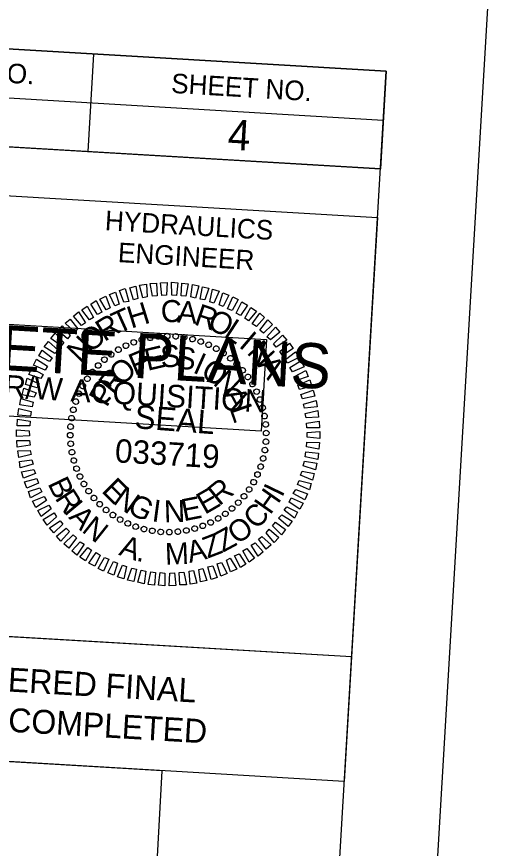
# Model space of a CAD drawing. Extents: x 2010737 to 2012732, y 444258 to 445456.
# Drawn here: x 2012611.3 to 2012732.3, y 445134 to 445346.8 of the extents above; entities that cross this region are included whole.
import ezdxf

# ---------------------------------------------------------------- set-up
doc = ezdxf.new("R2010")
doc.units = 0
for name, color, linetype in [('Sheet Clip Boundary CELL', 7, 'Continuous'), ('Sheet Data Field CELL', 7, 'Continuous'), ('Sheet Plan And Profile CELL', 7, 'Continuous'), ('Sheet Plot Border Outside CELL', 7, 'Continuous'), ('Sheet Professional Seal CELL', 7, 'Continuous'), ('Sheet Profile Grid Minor CELL', 7, 'Continuous'), ('Sheet Sticker Exception Certification CELL', 7, 'Continuous'), ('Sheet Sticker Incomplete CELL', 7, 'Continuous')]:
    doc.layers.add(name, color=color, linetype=linetype)

msp = doc.modelspace()

# ---------------------------------------------------------------- linework, layer by layer
at = {"layer": 'Sheet Clip Boundary CELL'}
msp.add_lwpolyline([(2011147.85, 444375), (2012145.7, 444317.47), (2012151.4, 444414.1), (2011981.99, 444424.08), (2012065.05, 444531.98), (2012116.09, 444528.98), (2012447, 444433.71), (2012447.13, 444434.15), (2012512.37, 444430.3), (2012650.6, 444422.19), (2012665.49, 444675.78), (2012620.99, 444678.39), (2012629.52, 444823.68), (2012643.65, 445063.27), (2012648.58, 445153.9), (2012495.5, 445162.92), (2012502.28, 445278.05), (2012302.58, 445289.82), (2012278.52, 445262.33), (2012176.97, 445268.45), (2011765.99, 445293.2), (2011771.61, 445387.92), (2011477.93, 445405.24)], dxfattribs=at)
at = {"layer": 'Sheet Plan And Profile CELL'}
for p, q in [((2012631.04, 445337.21), (2012629.57, 445312.26)), ((2012505.47, 445332.09), (2012705.17, 445320.32)), ((2012504.73, 445319.61), (2012704.44, 445307.84))]:
    msp.add_line(p, q, dxfattribs=at)
for points in [[(2012705.91, 445332.85), (2011208.51, 445421.12), (2011146.72, 444372.94), (2012644.12, 444284.67)], [(2012506.21, 445344.62), (2012705.91, 445332.85), (2012704.44, 445307.84), (2012504.73, 445319.61)], [(2012603.87, 445301.25), (2012703.7, 445295.36), (2012697.08, 445183.06), (2012597.25, 445188.94)]]:
    msp.add_lwpolyline(points, close=True, dxfattribs=at)
at = {"layer": 'Sheet Plot Border Outside CELL'}
msp.add_lwpolyline([(2010970.55, 444358.28), (2012667.61, 444258.24), (2012732.34, 445356.33), (2011035.28, 445456.37)], close=True, dxfattribs=at)
at = {"layer": 'Sheet Professional Seal CELL'}
for p, q in [((2012647.71, 445264.93), (2012647.71, 445264.93)), ((2012649.87, 445265.11), (2012649.87, 445265.11)), ((2012652.07, 445265.03), (2012652.07, 445265.03)), ((2012641.31, 445263.51), (2012641.31, 445263.51)), ((2012643.35, 445264.19), (2012643.35, 445264.19)), ((2012645.49, 445264.66), (2012645.49, 445264.66)), ((2012654.26, 445264.75), (2012654.26, 445264.75)), ((2012656.38, 445264.27), (2012656.38, 445264.27)), ((2012658.45, 445263.7), (2012658.45, 445263.7)), ((2012660.51, 445262.88), (2012660.51, 445262.88)), ((2012637.34, 445261.59), (2012637.34, 445261.59)), ((2012639.31, 445262.62), (2012639.31, 445262.62)), ((2012662.45, 445261.86), (2012662.45, 445261.86)), ((2012664.34, 445260.75), (2012664.34, 445260.75)), ((2012633.79, 445259.04), (2012633.79, 445259.04)), ((2012635.52, 445260.44), (2012635.52, 445260.44)), ((2012666.06, 445259.39), (2012666.06, 445259.39)), ((2012632.2, 445257.58), (2012632.2, 445257.58)), ((2012667.73, 445257.94), (2012667.73, 445257.94)), ((2012669.19, 445256.36), (2012669.19, 445256.36)), ((2012630.75, 445255.92), (2012630.75, 445255.92)), ((2012670.59, 445254.62), (2012670.59, 445254.62)), ((2012628.28, 445252.31), (2012628.28, 445252.31)), ((2012629.39, 445254.19), (2012629.39, 445254.19)), ((2012671.73, 445252.8), (2012671.73, 445252.8)), ((2012627.26, 445250.36), (2012627.26, 445250.36)), ((2012672.77, 445250.84), (2012672.77, 445250.84)), ((2012626.44, 445248.31), (2012626.44, 445248.31)), ((2012673.65, 445248.83), (2012673.65, 445248.83)), ((2012625.87, 445246.24), (2012625.87, 445246.24)), ((2012674.33, 445246.79), (2012674.33, 445246.79)), ((2012625.39, 445244.11), (2012625.39, 445244.11)), ((2012674.81, 445244.65), (2012674.81, 445244.65)), ((2012625.11, 445241.92), (2012625.11, 445241.92)), ((2012675.08, 445242.43), (2012675.08, 445242.43)), ((2012625.03, 445239.73), (2012625.03, 445239.73)), ((2012650.14, 445240), (2012650.14, 445240)), ((2012675.25, 445240.27), (2012675.25, 445240.27)), ((2012625.21, 445237.56), (2012625.21, 445237.56)), ((2012675.17, 445238.07), (2012675.17, 445238.07)), ((2012625.48, 445235.34), (2012625.48, 445235.34)), ((2012674.89, 445235.88), (2012674.89, 445235.88)), ((2012625.95, 445233.21), (2012625.95, 445233.21)), ((2012674.42, 445233.76), (2012674.42, 445233.76)), ((2012626.63, 445231.17), (2012626.63, 445231.17)), ((2012673.84, 445231.69), (2012673.84, 445231.69)), ((2012627.52, 445229.16), (2012627.52, 445229.16)), ((2012673.02, 445229.63), (2012673.02, 445229.63)), ((2012628.55, 445227.2), (2012628.55, 445227.2)), ((2012672.01, 445227.69), (2012672.01, 445227.69)), ((2012629.7, 445225.38), (2012629.7, 445225.38)), ((2012670.89, 445225.8), (2012670.89, 445225.8)), ((2012631.1, 445223.64), (2012631.1, 445223.64)), ((2012668.09, 445222.41), (2012668.09, 445222.41)), ((2012669.54, 445224.08), (2012669.54, 445224.08)), ((2012632.56, 445222.05), (2012632.56, 445222.05)), ((2012634.22, 445220.6), (2012634.22, 445220.6)), ((2012666.5, 445220.95), (2012666.5, 445220.95)), ((2012635.95, 445219.25), (2012635.95, 445219.25)), ((2012637.83, 445218.13), (2012637.83, 445218.13)), ((2012662.94, 445218.41), (2012662.94, 445218.41)), ((2012664.76, 445219.55), (2012664.76, 445219.55)), ((2012639.78, 445217.12), (2012639.78, 445217.12)), ((2012641.83, 445216.3), (2012641.83, 445216.3)), ((2012658.97, 445216.49), (2012658.97, 445216.49)), ((2012660.98, 445217.37), (2012660.98, 445217.37)), ((2012643.9, 445215.72), (2012643.9, 445215.72)), ((2012646.03, 445215.25), (2012646.03, 445215.25)), ((2012648.22, 445214.97), (2012648.22, 445214.97)), ((2012650.42, 445214.89), (2012650.42, 445214.89)), ((2012652.58, 445215.06), (2012652.58, 445215.06)), ((2012654.8, 445215.33), (2012654.8, 445215.33)), ((2012656.93, 445215.81), (2012656.93, 445215.81))]:
    msp.add_line(p, q, dxfattribs=at)
for points in [[(2012641.25, 445274.38), (2012640.28, 445277.44), (2012641.85, 445277.8), (2012642.32, 445274.67)], [(2012643.68, 445274.89), (2012642.82, 445278.09), (2012644.54, 445278.34), (2012644.75, 445275.08)], [(2012646.11, 445275.3), (2012645.5, 445278.54), (2012647.16, 445278.59), (2012647.32, 445275.38)], [(2012648.53, 445275.45), (2012648.17, 445278.68), (2012649.87, 445278.78), (2012649.73, 445275.53)], [(2012651.04, 445275.56), (2012650.98, 445278.82), (2012652.62, 445278.67), (2012652.23, 445275.44)], [(2012653.43, 445275.37), (2012653.62, 445278.61), (2012655.27, 445278.46), (2012654.62, 445275.25)], [(2012655.92, 445275.07), (2012656.31, 445278.3), (2012657.94, 445277.91), (2012657.1, 445274.8)], [(2012658.29, 445274.53), (2012658.93, 445277.7), (2012660.56, 445277.35), (2012659.48, 445274.31)], [(2012636.5, 445272.81), (2012635.07, 445275.7), (2012636.66, 445276.3), (2012637.62, 445273.19)], [(2012638.76, 445273.73), (2012637.63, 445276.7), (2012639.16, 445277.21), (2012640.02, 445273.95)], [(2012660.8, 445273.83), (2012661.49, 445277.04), (2012663.17, 445276.54), (2012661.84, 445273.52)], [(2012663.16, 445273.04), (2012664.09, 445276.09), (2012665.61, 445275.5), (2012664.19, 445272.63)], [(2012632.01, 445270.62), (2012630.32, 445273.27), (2012631.67, 445274.14), (2012633.15, 445271.15)], [(2012634.28, 445271.74), (2012632.6, 445274.54), (2012634.19, 445275.25), (2012635.27, 445272.28)], [(2012665.35, 445272.01), (2012666.69, 445275.09), (2012668.05, 445274.4), (2012666.48, 445271.59)], [(2012667.54, 445270.93), (2012668.96, 445273.8), (2012670.47, 445273.01), (2012668.61, 445270.31)], [(2012627.94, 445267.8), (2012625.87, 445270.13), (2012627.14, 445271.26), (2012628.93, 445268.45)], [(2012630.03, 445269.23), (2012628.02, 445271.75), (2012629.43, 445272.72), (2012631.01, 445269.83)], [(2012669.77, 445269.64), (2012671.29, 445272.41), (2012672.73, 445271.47), (2012670.68, 445268.99)], [(2012626.19, 445266.15), (2012623.77, 445268.35), (2012625.08, 445269.42), (2012627.04, 445266.9)], [(2012671.64, 445268.18), (2012673.56, 445270.97), (2012674.79, 445269.85), (2012672.7, 445267.52)], [(2012673.6, 445266.56), (2012675.61, 445269.2), (2012676.84, 445268.03), (2012674.5, 445265.81)], [(2012624.33, 445264.36), (2012621.85, 445266.46), (2012623.03, 445267.69), (2012625.08, 445265.22)], [(2012675.4, 445264.9), (2012677.6, 445267.38), (2012678.73, 445266.11), (2012676.31, 445264.1)], [(2012622.72, 445262.55), (2012620.13, 445264.41), (2012621.16, 445265.8), (2012623.43, 445263.46)], [(2012677.1, 445263.05), (2012679.38, 445265.27), (2012680.51, 445264), (2012677.8, 445262.21)], [(2012621.11, 445260.64), (2012618.4, 445262.3), (2012619.48, 445263.64), (2012621.96, 445261.49)], [(2012678.74, 445261.15), (2012681.17, 445263.26), (2012682.13, 445261.85), (2012679.38, 445260.11)], [(2012619.78, 445258.57), (2012617.01, 445259.98), (2012617.85, 445261.49), (2012620.44, 445259.48)], [(2012680.12, 445259.12), (2012682.69, 445261.07), (2012683.55, 445259.57), (2012680.66, 445258.13)], [(2012618.65, 445256.33), (2012615.62, 445257.66), (2012616.46, 445259.16), (2012619.21, 445257.4)], [(2012681.3, 445256.99), (2012684.05, 445258.73), (2012684.91, 445257.18), (2012681.94, 445255.95)], [(2012617.52, 445254.19), (2012614.48, 445255.27), (2012615.22, 445256.78), (2012618.13, 445255.21)], [(2012616.63, 445251.84), (2012613.58, 445252.67), (2012614.02, 445254.3), (2012617.09, 445252.87)], [(2012682.47, 445254.72), (2012685.36, 445256.3), (2012685.92, 445254.72), (2012683.01, 445253.74)], [(2012683.34, 445252.52), (2012686.37, 445253.84), (2012686.92, 445252.2), (2012683.77, 445251.39)], [(2012615.84, 445249.48), (2012612.77, 445250.06), (2012613.22, 445251.74), (2012616.3, 445250.51)], [(2012684.1, 445250.12), (2012687.22, 445251.24), (2012687.68, 445249.66), (2012684.53, 445249.04)], [(2012615.29, 445246.96), (2012612.12, 445247.45), (2012612.42, 445249.13), (2012615.61, 445248.14)], [(2012684.75, 445247.67), (2012688.02, 445248.63), (2012688.22, 445246.97), (2012685.04, 445246.61)], [(2012614.9, 445244.58), (2012611.66, 445244.87), (2012611.86, 445246.51), (2012615.07, 445245.77)], [(2012685.21, 445245.24), (2012688.41, 445246.01), (2012688.61, 445244.29), (2012685.45, 445244.18)], [(2012614.7, 445242.09), (2012611.45, 445242.13), (2012611.55, 445243.83), (2012614.77, 445243.28)], [(2012685.52, 445242.82), (2012688.81, 445243.33), (2012688.86, 445241.62), (2012685.65, 445241.61)], [(2012614.61, 445239.59), (2012611.34, 445239.38), (2012611.34, 445241.08), (2012614.58, 445240.79)], [(2012685.68, 445240.41), (2012688.95, 445240.62), (2012688.95, 445238.91), (2012685.71, 445239.2)], [(2012614.77, 445237.17), (2012611.48, 445236.67), (2012611.43, 445238.37), (2012614.64, 445238.38)], [(2012685.58, 445237.91), (2012688.83, 445237.87), (2012688.73, 445236.17), (2012685.51, 445236.71)], [(2012615.07, 445234.75), (2012611.87, 445233.99), (2012611.67, 445235.7), (2012614.84, 445235.82)], [(2012685.38, 445235.42), (2012688.62, 445235.13), (2012688.43, 445233.48), (2012685.21, 445234.22)], [(2012615.53, 445232.32), (2012612.27, 445231.36), (2012612.07, 445233.03), (2012615.24, 445233.39)], [(2012684.99, 445233.04), (2012688.17, 445232.55), (2012687.87, 445230.86), (2012684.67, 445231.85)], [(2012616.19, 445229.88), (2012613.07, 445228.76), (2012612.61, 445230.34), (2012615.75, 445230.96)], [(2012684.44, 445230.51), (2012687.52, 445229.93), (2012687.07, 445228.25), (2012683.98, 445229.49)], [(2012616.95, 445227.48), (2012613.92, 445226.16), (2012613.36, 445227.79), (2012616.51, 445228.61)], [(2012683.65, 445228.16), (2012686.71, 445227.32), (2012686.26, 445225.7), (2012683.19, 445227.13)], [(2012617.82, 445225.27), (2012614.92, 445223.69), (2012614.36, 445225.28), (2012617.28, 445226.26)], [(2012682.76, 445225.8), (2012685.81, 445224.72), (2012685.07, 445223.21), (2012682.15, 445224.79)], [(2012618.99, 445223), (2012616.23, 445221.26), (2012615.37, 445222.81), (2012618.35, 445224.04)], [(2012681.64, 445223.67), (2012684.66, 445222.34), (2012683.82, 445220.83), (2012681.07, 445222.6)], [(2012620.17, 445220.88), (2012617.6, 445218.93), (2012616.73, 445220.43), (2012619.62, 445221.86)], [(2012680.5, 445221.43), (2012683.27, 445220.01), (2012682.43, 445218.51), (2012679.85, 445220.52)], [(2012621.55, 445218.84), (2012619.12, 445216.73), (2012618.15, 445218.14), (2012620.91, 445219.88)], [(2012679.18, 445219.35), (2012681.89, 445217.69), (2012680.8, 445216.35), (2012678.33, 445218.5)], [(2012623.19, 445216.94), (2012620.9, 445214.72), (2012619.78, 445215.99), (2012622.49, 445217.79)], [(2012677.56, 445217.45), (2012680.16, 445215.59), (2012679.12, 445214.2), (2012676.86, 445216.54)], [(2012624.88, 445215.09), (2012622.68, 445212.62), (2012621.56, 445213.88), (2012623.98, 445215.9)], [(2012626.69, 445213.43), (2012624.68, 445210.8), (2012623.45, 445211.97), (2012625.78, 445214.19)], [(2012674.1, 445213.84), (2012676.52, 445211.65), (2012675.2, 445210.57), (2012673.25, 445213.09)], [(2012675.95, 445215.64), (2012678.43, 445213.54), (2012677.26, 445212.3), (2012675.2, 445214.78)], [(2012628.65, 445211.81), (2012626.73, 445209.02), (2012625.49, 445210.15), (2012627.58, 445212.48)], [(2012672.35, 445212.19), (2012674.41, 445209.87), (2012673.14, 445208.74), (2012671.36, 445211.55)], [(2012630.51, 445210.35), (2012629, 445207.59), (2012627.55, 445208.52), (2012629.6, 445211.01)], [(2012632.74, 445209.07), (2012631.32, 445206.2), (2012629.82, 445206.99), (2012631.68, 445209.68)], [(2012670.26, 445210.76), (2012672.26, 445208.24), (2012670.85, 445207.27), (2012669.27, 445210.17)], [(2012634.93, 445207.99), (2012633.6, 445204.91), (2012632.24, 445205.59), (2012633.81, 445208.4)], [(2012666, 445208.26), (2012667.69, 445205.46), (2012666.1, 445204.75), (2012665.02, 445207.72)], [(2012668.27, 445209.38), (2012669.97, 445206.72), (2012668.62, 445205.85), (2012667.14, 445208.84)], [(2012637.13, 445206.96), (2012636.19, 445203.91), (2012634.68, 445204.5), (2012636.1, 445207.37)], [(2012639.48, 445206.17), (2012638.79, 445202.95), (2012637.12, 445203.45), (2012638.45, 445206.48)], [(2012642, 445205.47), (2012641.36, 445202.3), (2012639.73, 445202.65), (2012640.81, 445205.69)], [(2012659.03, 445205.62), (2012660.01, 445202.55), (2012658.43, 445202.19), (2012657.97, 445205.33)], [(2012661.53, 445206.27), (2012662.65, 445203.3), (2012661.12, 445202.79), (2012660.26, 445206.04)], [(2012663.79, 445207.19), (2012665.22, 445204.3), (2012663.63, 445203.69), (2012662.66, 445206.8)], [(2012644.37, 445204.93), (2012643.98, 445201.69), (2012642.35, 445202.09), (2012643.18, 445205.2)], [(2012646.86, 445204.63), (2012646.66, 445201.39), (2012645.02, 445201.53), (2012645.66, 445204.75)], [(2012649.25, 445204.44), (2012649.31, 445201.18), (2012647.66, 445201.33), (2012648.05, 445204.56)], [(2012651.76, 445204.54), (2012652.12, 445201.31), (2012650.41, 445201.21), (2012650.55, 445204.46)], [(2012654.17, 445204.7), (2012654.78, 445201.46), (2012653.13, 445201.41), (2012652.97, 445204.62)], [(2012656.6, 445205.11), (2012657.46, 445201.9), (2012655.75, 445201.65), (2012655.54, 445204.92)]]:
    msp.add_lwpolyline(points, close=True, dxfattribs=at)
for centre, major_axis in [((2012643.39, 445264.15), (-0.194, 0.693)), ((2012645.52, 445264.65), (-0.133, 0.708)), ((2012647.68, 445264.96), (-0.071, 0.717)), ((2012649.87, 445265.08), (-0.008, 0.72)), ((2012652.06, 445265), (0.055, 0.718)), ((2012654.23, 445264.74), (0.117, 0.71)), ((2012656.37, 445264.29), (0.179, 0.697)), ((2012639.3, 445262.61), (-0.311, 0.649)), ((2012641.31, 445263.47), (-0.254, 0.674)), ((2012658.46, 445263.66), (0.239, 0.679)), ((2012660.49, 445262.84), (0.297, 0.656)), ((2012635.53, 445260.38), (-0.419, 0.585)), ((2012637.37, 445261.58), (-0.367, 0.62)), ((2012662.44, 445261.85), (0.353, 0.627)), ((2012664.3, 445260.7), (0.407, 0.594)), ((2012633.81, 445259.03), (-0.469, 0.546)), ((2012666.05, 445259.39), (0.457, 0.557)), ((2012667.68, 445257.93), (0.504, 0.515)), ((2012630.76, 445255.91), (-0.557, 0.457)), ((2012632.22, 445257.54), (-0.515, 0.504)), ((2012669.18, 445256.33), (0.546, 0.469)), ((2012629.44, 445254.16), (-0.594, 0.407)), ((2012670.53, 445254.61), (0.585, 0.419)), ((2012628.29, 445252.3), (-0.627, 0.353)), ((2012671.72, 445252.77), (0.62, 0.367)), ((2012627.3, 445250.35), (-0.656, 0.297)), ((2012672.76, 445250.85), (0.649, 0.311)), ((2012626.48, 445248.32), (-0.679, 0.239)), ((2012673.62, 445248.83), (0.674, 0.254)), ((2012625.85, 445246.22), (-0.697, 0.179)), ((2012674.3, 445246.75), (0.693, 0.194)), ((2012625.4, 445244.08), (-0.71, 0.117)), ((2012674.79, 445244.62), (0.708, 0.133)), ((2012625.14, 445241.91), (-0.718, 0.055)), ((2012675.1, 445242.46), (0.717, 0.071)), ((2012625.06, 445239.72), (-0.72, -0.008)), ((2012675.22, 445240.27), (0.72, 0.008)), ((2012625.18, 445237.54), (-0.717, -0.071)), ((2012675.15, 445238.09), (0.718, -0.055)), ((2012625.49, 445235.37), (-0.708, -0.133)), ((2012674.89, 445235.91), (0.71, -0.117)), ((2012625.99, 445233.24), (-0.693, -0.194)), ((2012674.44, 445233.77), (0.697, -0.179)), ((2012626.67, 445231.16), (-0.674, -0.254)), ((2012673.8, 445231.68), (0.679, -0.239)), ((2012627.53, 445229.15), (-0.649, -0.311)), ((2012672.99, 445229.65), (0.656, -0.297)), ((2012628.56, 445227.22), (-0.62, -0.367)), ((2012670.84, 445225.84), (0.594, -0.407)), ((2012672, 445227.7), (0.627, -0.353)), ((2012629.76, 445225.39), (-0.585, -0.419)), ((2012631.11, 445223.67), (-0.546, -0.469)), ((2012669.53, 445224.09), (0.557, -0.457)), ((2012632.6, 445222.07), (-0.504, -0.515)), ((2012668.07, 445222.46), (0.515, -0.504)), ((2012634.23, 445220.61), (-0.457, -0.557)), ((2012664.75, 445219.61), (0.419, -0.585)), ((2012666.47, 445220.96), (0.469, -0.546)), ((2012635.98, 445219.3), (-0.407, -0.594)), ((2012637.84, 445218.14), (-0.353, -0.627)), ((2012660.99, 445217.39), (0.311, -0.649)), ((2012662.92, 445218.42), (0.367, -0.62)), ((2012639.79, 445217.15), (-0.297, -0.656)), ((2012641.82, 445216.34), (-0.239, -0.679)), ((2012643.92, 445215.7), (-0.179, -0.697)), ((2012646.06, 445215.25), (-0.117, -0.71)), ((2012654.77, 445215.35), (0.133, -0.708)), ((2012656.9, 445215.84), (0.194, -0.693)), ((2012658.98, 445216.53), (0.254, -0.674)), ((2012648.23, 445214.99), (-0.055, -0.718)), ((2012650.42, 445214.92), (0.008, -0.72)), ((2012652.6, 445215.04), (0.071, -0.717))]:
    msp.add_ellipse(centre, major_axis=major_axis, ratio=0.999708, dxfattribs=at)
at = {"layer": 'Sheet Sticker Exception Certification CELL'}
for p, q in [((2012497.38, 445194.85), (2012697.08, 445183.08)), ((2012697.08, 445183.06), (2012695.2, 445151.13)), ((2012695.2, 445151.15), (2012495.5, 445162.92))]:
    msp.add_line(p, q, dxfattribs=at)
at = {"layer": 'Sheet Sticker Incomplete CELL'}
msp.add_lwpolyline([(2012527.19, 445249.42), (2012528.57, 445272.88), (2012675.32, 445264.23), (2012673.94, 445240.77)], close=True, dxfattribs=at)

# ---------------------------------------------------------------- texts
at = {"layer": 'Sheet Data Field CELL'}
msp.add_text('4', height=7.75, rotation=356.6264, dxfattribs=at).set_placement((2012665.21, 445312.81))
at = {"layer": 'Sheet Plan And Profile CELL'}
for s, height, p in [('PROJECT REFERENCE NO.', 5.0001, (2012527.86, 445334.63)), ('SHEET NO.', 5, (2012650.79, 445327.28)), ('HYDRAULICS', 5, (2012633.84, 445292.17)), ('ENGINEER', 5, (2012637.17, 445284.01))]:
    msp.add_text(s, height=height, rotation=356.6264, dxfattribs=at).set_placement(p)
at = {"layer": 'Sheet Professional Seal CELL'}
for s, height, rotation, p in [('H', 5.64, 17.2459, (2012640.66, 445266.95)), ('C', 5.64, 2.8463, (2012648.37, 445268.5)), ('A', 5.64, 355.6467, (2012652.33, 445268.57)), ('T', 5.64, 24.4462, (2012637.32, 445265.5)), ('R', 5.64, 341.2475, (2012656.51, 445268.12)), ('O', 5.64, 334.0476, (2012659.81, 445267.18)), ('R', 5.64, 31.6469, (2012633.8, 445263.5)), ('L', 5.64, 326.8473, (2012664.09, 445265.07)), ('O', 5.64, 38.8482, (2012630.17, 445260.61)), ('N', 5.64, 46.0499, (2012627.7, 445257.85)), ('I', 5.64, 319.6466, (2012667.99, 445262.44)), ('S', 5.64, 3.882, (2012648.34, 445256.98)), ('N', 5.64, 312.4453, (2012670.05, 445260.76)), ('F', 5.64, 22.5935, (2012641.55, 445254.83)), ('E', 5.64, 13.2375, (2012644.83, 445256.14)), ('S', 5.64, 354.5268, (2012651.94, 445256.82)), ('I', 5.64, 335.816, (2012656.19, 445255.87)), ('O', 5.64, 41.3077, (2012638.08, 445252.08)), ('O', 5.64, 326.4599, (2012658.14, 445255.05)), ('A', 5.64, 305.2436, (2012672.82, 445257.64)), ('R', 5.64, 50.6661, (2012636.19, 445249.74)), ('N', 5.64, 317.103, (2012661.37, 445252.86)), ('P', 5.64, 60.0253, (2012634.41, 445246.64)), ('A', 5.64, 298.3867, (2012664.06, 445250.1)), ('SEAL', 5.998, 355.6264, (2012641.37, 445241.52)), ('L', 5.64, 289.0273, (2012665.8, 445246.54)), ('E', 5.64, 314.9033, (2012632.85, 445225.34)), ('N', 5.64, 324.2604, (2012635.69, 445222.47)), ('R', 5.64, 39.1078, (2012663.17, 445221.45)), ('E', 5.64, 29.7505, (2012659.49, 445219.31)), ('G', 5.64, 333.6167, (2012639.35, 445220)), ('I', 5.64, 352.3276, (2012645.77, 445217.72)), ('N', 5.64, 1.6828, (2012649.11, 445217.37)), ('E', 5.64, 11.0382, (2012654.09, 445217.68))]:
    msp.add_text(s, height=height, rotation=rotation, dxfattribs=at).set_placement(p)
at = {"layer": 'Sheet Profile Grid Minor CELL'}
for s, height, rotation, p in [('033719', 5.998, 356.6264, (2012636.38, 445232.79)), ('B', 5.5, 295.7793, (2012619.2, 445227.36)), ('I', 5.5, 64.2191, (2012679.28, 445223.62)), ('R', 5.5, 302.9061, (2012621, 445223.61)), ('H', 5.5, 54.9743, (2012676.27, 445219.15)), ('I', 5.5, 309.8326, (2012623.19, 445220.22)), ('A', 5.5, 313.353, (2012624.46, 445218.6)), ('C', 5.5, 46.1015, (2012672.75, 445215.37)), ('N', 5.5, 321.5388, (2012627.77, 445215.16)), ('O', 5.5, 35.397, (2012667.78, 445211.6)), ('Z', 5.5, 28.2703, (2012664.12, 445209.63)), ('Z', 5.5, 21.1435, (2012660.24, 445208.13)), ('A', 5.5, 340.9157, (2012637.27, 445209.15)), ('M', 5.5, 2.2818, (2012649.4, 445206.58)), ('A', 5.5, 12.9577, (2012655.6, 445207.02)), ('.', 5.5, 349.1015, (2012641.8, 445207.63))]:
    msp.add_text(s, height=height, rotation=rotation, dxfattribs=at).set_placement(p)
at = {"layer": 'Sheet Sticker Exception Certification CELL'}
for s, p in [('DOCUMENT NOT CONSIDERED FINAL', (2012508.16, 445180.11)), ('UNLESS ALL SIGNATURES COMPLETED', (2012501.83, 445170.2))]:
    msp.add_text(s, height=6.124, rotation=356.6264, dxfattribs=at).set_placement(p)
at = {"layer": 'Sheet Sticker Incomplete CELL'}
for s, height, p in [('INCOMPLETE PLANS', 11.52, (2012536.81, 445260.57)), ('DO NOT USE FOR R/W ACQUISITION', 5.76, (2012539.65, 445253.45))]:
    msp.add_text(s, height=height, rotation=356.6264, dxfattribs=at).set_placement(p)

doc.saveas('drawing.dxf')
